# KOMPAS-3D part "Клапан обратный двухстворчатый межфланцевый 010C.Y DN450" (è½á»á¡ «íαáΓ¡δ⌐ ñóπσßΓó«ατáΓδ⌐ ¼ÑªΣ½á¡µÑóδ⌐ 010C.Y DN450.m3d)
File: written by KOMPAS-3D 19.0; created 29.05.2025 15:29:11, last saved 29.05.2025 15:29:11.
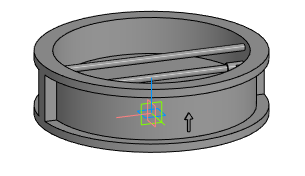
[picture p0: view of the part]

Document properties: Полное имя файла: E:\Dendor Работа Сачек\3D для проекитирвщиков\5.2 Тип 010C, 010C.Y Клапан обратный двухстворчатый межфланцевый\stp_Клапан обратный двухстворчатый межфланцевый 010C.Y\Клапан обратный двухстворчатый межфланцевый 010C.Y DN450.m3d

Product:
- Part/product: Клапан обратный двухстворчатый межфланцевый 010C.Y DN450

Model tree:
1. Операция без истории:1  (labels: Клапан обратный двухстворчатый межфланцевый 010C.Y DN450)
